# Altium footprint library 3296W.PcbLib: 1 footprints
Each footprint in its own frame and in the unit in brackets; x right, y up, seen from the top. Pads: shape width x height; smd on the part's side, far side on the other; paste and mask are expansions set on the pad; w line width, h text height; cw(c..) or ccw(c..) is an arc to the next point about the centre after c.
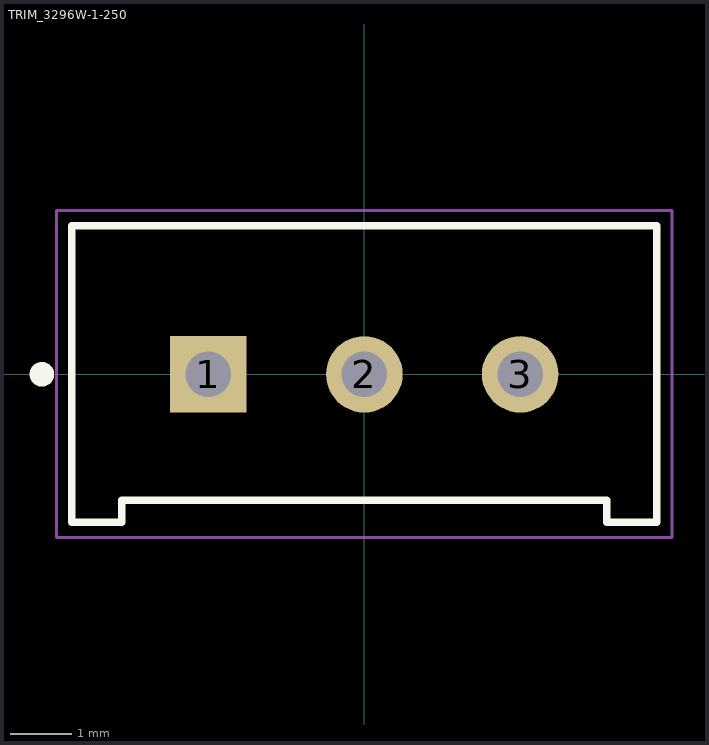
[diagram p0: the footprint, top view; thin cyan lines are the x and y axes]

## TRIM_3296W-1-250 [mm]
pads (3):
  rect 1.248x1.248 hole 0.74: 1(-2.54,0)
  round 1.248 hole 0.74: 2(0,0) 3(2.54,0)
Top Overlay:
  circle w0.2: c-5.25,0 r0.1
  lines w0.127: -4.765,-2.41 -3.95,-2.41 -3.95,-2.05 3.95,-2.05 3.95,-2.41 4.765,-2.41 4.765,2.42 -4.765,2.42 -4.765,-2.41
Mechanical 15:
  lines w0.05: -5.015,-2.66 -5.015,2.67 5.015,2.67 5.015,-2.66 -5.015,-2.66
3D body "3296W.STEP": height 11.55, standoff -7.72, extent -4.831,-2.415 4.699,2.415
